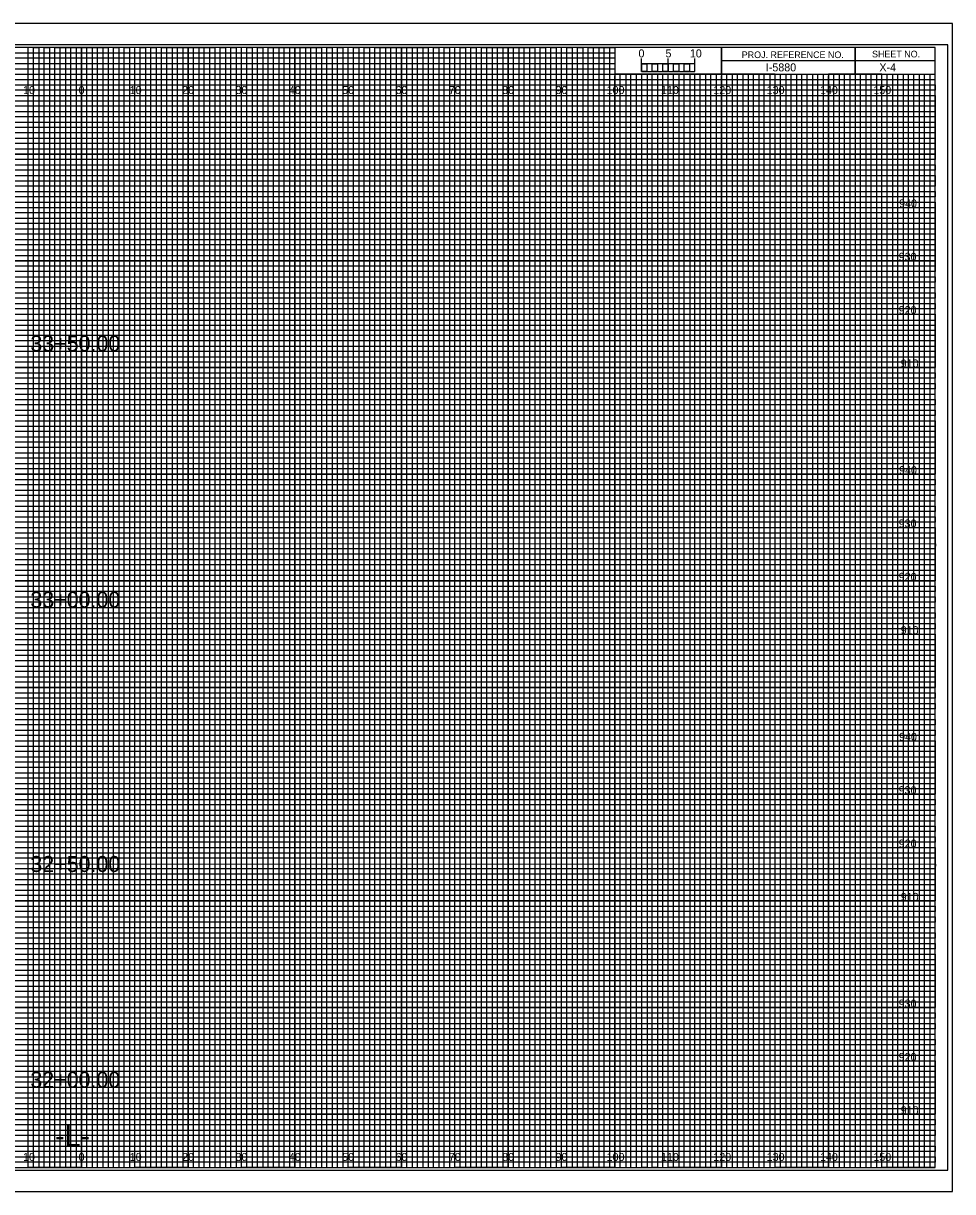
# Model space of a CAD drawing. Extents: x -13 to 323, y -4 to 3074.
# Drawn here: x 149.1 to 323.3, y 435.5 to 654.5 of the extents above; entities that cross this region are included whole.
import ezdxf

# ---------------------------------------------------------------- set-up
doc = ezdxf.new("R2010")
doc.units = 0
for name, color, linetype in [('Prop XS Alignment Label', 7, 'Continuous'), ('Prop XS Bar Scale Labels', 7, 'Continuous'), ('Prop XS Elevation Labels', 7, 'Continuous'), ('Prop XS Offset Labels', 7, 'Continuous'), ('Prop XS Project Number', 7, 'Continuous'), ('Prop XS Sheet Number', 7, 'Continuous'), ('Prop XS Station Labels', 7, 'Continuous'), ('Sheet Cross Section CELL', 7, 'Continuous'), ('Sheet Cross Section Grid Major CELL', 7, 'Continuous'), ('Sheet Cross Section Grid Middle CELL', 7, 'Continuous'), ('Sheet Cross Section Grid Minor 1 CELL', 7, 'Continuous'), ('Sheet Cross Section Grid Minor 2 CELL', 7, 'Continuous'), ('Sheet Cross Section Scale CELL', 7, 'Continuous'), ('Sheet Cutting Line CELL', 7, 'Continuous'), ('Sheet DOT Grid CELL', 7, 'Continuous'), ('Sheet Plot Border Inside CELL', 7, 'Continuous'), ('Sheet Plot Border Outside CELL', 7, 'Continuous')]:
    doc.layers.add(name, color=color, linetype=linetype)

msp = doc.modelspace()

# ---------------------------------------------------------------- linework, layer by layer
at = {"layer": 'Sheet Cross Section CELL'}
for p, q in [((305, 650), (305, 645)), ((305, 645), (305, 650)), ((280, 647.5), (280, 645)), ((320, 647.49), (280, 647.49)), ((280, 645), (320, 645))]:
    msp.add_line(p, q, dxfattribs=at)
for points in [[(320, 650), (0, 650), (0, 440), (320, 440)], [(280, 650), (260, 650), (260, 645.03), (280, 645.03)], [(320, 650), (280, 650), (280, 645), (320, 645)]]:
    msp.add_lwpolyline(points, close=True, dxfattribs=at)
at = {"layer": 'Sheet Cross Section Grid Major CELL'}
for p, q in [((150, 650), (140, 650)), ((150, 440), (150, 650)), ((170, 650), (160, 650)), ((160, 650), (160, 440)), ((170, 440), (170, 650)), ((190, 650), (180, 650)), ((180, 650), (180, 440)), ((190, 440), (190, 650)), ((210, 650), (200, 650)), ((200, 650), (200, 440)), ((210, 440), (210, 650)), ((230, 650), (220, 650)), ((220, 650), (220, 440)), ((230, 440), (230, 650)), ((250, 650), (240, 650)), ((240, 650), (240, 440)), ((250, 440), (250, 650)), ((260, 650), (260, 440)), ((270, 440), (270, 645)), ((290, 645), (280, 645)), ((280, 645), (280, 440)), ((290, 440), (290, 645)), ((310, 645), (300, 645)), ((300, 645), (300, 440)), ((310, 440), (310, 645)), ((160, 440), (150, 440)), ((180, 440), (170, 440)), ((200, 440), (190, 440)), ((220, 440), (210, 440)), ((240, 440), (230, 440)), ((260, 440), (250, 440)), ((280, 440), (270, 440)), ((300, 440), (290, 440)), ((320, 440), (310, 440)), ((320, 440), (320, 440))]:
    msp.add_line(p, q, dxfattribs=at)
for points in [[(0, 640), (320, 640), (320, 630), (0, 630)], [(0, 620), (320, 620), (320, 610), (0, 610)], [(0, 600), (320, 600), (320, 590), (0, 590)], [(0, 580), (320, 580), (320, 570), (0, 570)], [(0, 560), (320, 560), (320, 550), (0, 550)], [(0, 540), (320, 540), (320, 530), (0, 530)], [(0, 520), (320, 520), (320, 510), (0, 510)], [(0, 500), (320, 500), (320, 490), (0, 490)], [(0, 480), (320, 480), (320, 470), (0, 470)], [(0, 460), (320, 460), (320, 450), (0, 450)]]:
    msp.add_lwpolyline(points, dxfattribs=at)
at = {"layer": 'Sheet Cross Section Grid Middle CELL'}
for points in [[(145, 440), (155, 440), (155, 650), (165, 650), (165, 440), (175, 440), (175, 650), (185, 650), (185, 440), (195, 440), (195, 650), (205, 650), (205, 440), (215, 440), (215, 650), (225, 650), (225, 440), (235, 440), (235, 650), (245, 650), (245, 440), (255, 440), (255, 650), (259.93, 650), (260, 650), (260, 645), (264.99, 645), (264.99, 440), (275, 440), (275, 645), (285, 645), (285, 440), (295, 440), (295, 645), (305, 645), (305, 440), (315, 440), (315, 645)], [(0, 645), (275, 645)], [(0, 625), (320, 625), (320, 635), (0, 635)], [(0, 605), (320, 605), (320, 615), (0, 615)], [(0, 585), (320, 585), (320, 595), (0, 595)], [(0, 565), (320, 565), (320, 575), (0, 575)], [(0, 545), (320, 545), (320, 555), (0, 555)], [(0, 525), (320, 525), (320, 535), (0, 535)], [(0, 505), (320, 505), (320, 515), (0, 515)], [(0, 485), (320, 485), (320, 495), (0, 495)], [(0, 465), (320, 465), (320, 475), (0, 475)], [(0, 445), (320, 445), (320, 455), (0, 455)]]:
    msp.add_lwpolyline(points, dxfattribs=at)
at = {"layer": 'Sheet Cross Section Grid Minor 1 CELL'}
for p, q in [((0, 649), (260, 649)), ((260, 649), (260, 647.98)), ((260, 647.98), (0, 647.98)), ((0, 647), (260, 647)), ((260, 647), (260, 645.89)), ((260, 645.89), (0, 645.89)), ((0, 644), (320, 644))]:
    msp.add_line(p, q, dxfattribs=at)
for points in [[(0, 643), (270, 643), (320, 643), (320, 642), (0, 642)], [(0, 641), (320, 641), (320, 639), (0, 639)], [(0, 638), (320, 638), (320, 637), (0, 636.98)], [(0, 636), (320, 636), (320, 634), (0, 634)], [(0, 633), (320, 633), (320, 632), (0, 632)], [(0, 631), (320, 631), (320, 629), (0, 629)], [(0, 628), (320, 628), (320, 627), (0, 627)], [(0, 626), (320, 626), (320, 624), (0, 624)], [(0, 623), (320, 623), (320, 622), (0, 622)], [(0, 621), (320, 621), (320, 619), (0, 619)], [(0, 618), (320, 618), (320, 617), (0, 617)], [(0, 616), (320, 616), (320, 613.95), (320, 613), (320, 612), (0, 612)], [(0, 614), (320, 614), (320, 613), (0, 613)], [(0, 611), (320, 611), (320, 609), (0, 609.03)], [(0, 609.03), (320, 609), (320, 608), (0, 608)], [(0, 607), (320, 607), (320, 606), (0, 606)], [(0, 604), (320, 604), (320, 603), (0, 603)], [(0, 602), (320, 602), (320, 601), (0, 601)], [(-0.07, 598.89), (320, 598.89), (320, 597.88), (-0.07, 597.88)], [(0, 597), (320, 597), (320, 596), (0, 596)], [(0, 594), (320, 594), (320, 593), (0, 593)], [(0, 592), (320, 592), (320, 591), (0, 591)], [(0, 589), (320, 589), (320, 588), (0, 588)], [(0, 587), (320, 587), (320, 586), (0, 586)], [(0, 584), (320, 584), (320, 583), (0, 583)], [(0, 582), (320, 582), (320, 581), (0, 581)], [(0, 579), (320, 579), (319.99, 577.98), (0, 578)], [(0, 577), (320, 577), (320, 576), (0, 576)], [(0, 574), (320, 574), (320, 573), (0, 573)], [(0, 572), (320, 572), (320, 571), (0, 571)], [(0, 569), (320, 569), (320, 568), (0, 568)], [(0, 567), (320, 567), (320, 566), (0, 566)], [(0, 564), (320, 564), (320, 563), (0, 563)], [(0, 562), (320, 562), (320, 561), (0, 561)], [(0, 559), (320, 559), (320, 558), (0, 558)], [(0, 556.99), (320.07, 556.91), (320, 556), (0, 556)], [(0, 554), (320, 554), (320, 553), (0, 553)], [(0, 552), (320, 552), (320, 551), (0, 551)], [(0, 549), (320, 549), (320, 548), (0, 548)], [(0, 547), (320, 547), (320, 546), (0, 546)], [(0, 544), (320, 544), (320, 543), (0, 543)], [(0, 542), (320, 542), (320, 541), (0, 541)], [(0, 539), (320, 539), (320, 538), (0, 538)], [(0, 537), (320, 537), (320, 536), (0, 536)], [(0, 534), (320, 534), (320, 533), (0, 533)], [(0, 532), (320, 532), (320, 531), (0, 531)], [(0, 529), (320, 529), (320, 528), (0, 528)], [(0, 527), (320, 527), (320, 526), (0, 526)], [(0, 524), (320, 524), (320, 523), (0, 523)], [(0, 522), (320, 522), (320, 521), (0, 521)], [(0, 519), (320, 519), (319.99, 517.98), (0, 518)], [(0, 517), (320, 517), (320, 516), (0, 516)], [(0, 514), (320, 514), (320, 513), (0, 513)], [(0, 512), (320, 512), (320, 511), (0, 511)], [(0, 509), (320, 509), (320, 508), (0, 508)], [(0, 507), (320, 507), (320, 506), (0, 506)], [(0, 504), (320, 504), (320, 503), (0, 503)], [(0, 502), (320, 502), (320, 501), (0, 501)], [(0, 499), (320, 499), (320, 498), (0, 498)], [(0, 496.99), (320.07, 496.91), (320, 496), (0, 496)], [(0, 494), (320, 494), (320, 493), (0, 493)], [(0, 492), (320, 492), (320, 491), (0, 491)], [(0, 489), (320, 489), (320, 488), (0, 488)], [(0, 487), (320, 487), (320, 486), (0, 486)], [(0, 484), (320, 484), (320, 483), (0, 483)], [(0, 482), (320, 482), (320, 481), (0, 481)], [(0, 479), (320, 479), (320, 478), (0, 478)], [(0, 477), (320, 477), (320, 476), (0, 476)], [(0, 474), (320, 474), (320, 473), (0, 473)], [(0, 472), (320, 472), (320, 471), (0, 471)], [(0, 469), (320, 469), (320, 468), (0, 468)], [(0, 467), (320, 467), (320, 466), (0, 466)], [(0, 464), (320, 464), (320, 463), (0, 463)], [(0, 462), (320, 462), (320, 461), (0, 461)], [(0, 459), (320, 459), (320, 458), (0, 458)], [(0, 457), (320, 457), (320, 456), (0, 456)], [(0, 454), (320, 454), (320, 453), (0, 453)], [(0, 452), (320, 452), (320, 451), (0, 451)], [(0, 449), (320, 449), (320, 448), (0, 448)], [(0, 447), (320, 447), (320, 446), (0, 446)], [(0, 444), (320, 444), (320, 443), (0, 443)], [(0, 442), (320, 442), (320, 441), (0, 441)]]:
    msp.add_lwpolyline(points, dxfattribs=at)
at = {"layer": 'Sheet Cross Section Grid Minor 2 CELL'}
for p, q in [((267, 645), (266.01, 645)), ((266.01, 645), (266.01, 440)), ((267, 440), (267, 645)), ((269, 645), (268, 645)), ((268, 645), (268, 440)), ((269, 440), (269, 645)), ((266.01, 440), (265, 440)), ((268, 440), (267, 440))]:
    msp.add_line(p, q, dxfattribs=at)
for points in [[(150, 440), (151, 440), (151, 650), (152, 650), (152, 440)], [(152, 440), (153, 440), (153, 650), (154, 650), (154, 440)], [(155, 440), (156, 440), (156, 650), (157, 650), (157, 440)], [(157, 440), (158, 440), (158, 650), (159, 650), (159, 440)], [(160, 440), (161, 440), (161, 650), (162, 650), (162, 440)], [(162, 440), (163, 440), (163, 650), (164, 650), (164, 440)], [(165, 440), (166, 440), (166, 650), (167, 650), (167, 440)], [(167, 440), (168, 440), (168, 650), (169, 650), (169, 440)], [(170, 440), (171, 440), (171, 650), (172, 650), (172, 440)], [(172, 440), (173, 440), (173, 650), (174, 650), (174, 440)], [(175, 440), (176, 440), (176, 650), (177, 650), (177, 440)], [(177, 440), (178, 440), (178, 650), (179, 650), (179, 440)], [(180, 440), (181, 440), (181, 650), (182, 650), (182, 440)], [(182, 440), (183, 440), (183, 650), (184, 650), (184, 440)], [(185, 440), (186, 440), (186, 650), (187, 650), (187, 440)], [(187, 440), (188, 440), (188, 650), (189, 650), (189, 440)], [(190, 440), (191, 440), (191, 650), (192, 650), (192, 440)], [(192, 440), (193, 440), (193, 650), (194, 650), (194, 440)], [(195, 440), (196, 440), (196, 650), (197, 650), (197, 440)], [(197, 440), (198, 440), (198, 650), (199, 650), (199, 440)], [(200, 440), (201, 440), (201, 650), (202, 650), (202, 440)], [(202, 440), (203, 440), (203, 650), (204, 650), (204, 440)], [(205, 440), (206, 440), (206, 650), (207, 650), (207, 440)], [(207, 440), (208, 440), (208, 650), (209, 650), (209, 440)], [(210, 440), (211, 440), (211, 650), (212, 650), (212, 440)], [(212, 440), (213, 440), (213, 650), (214, 650), (214, 440)], [(215, 440), (216, 440), (216, 650), (217, 650), (217, 440)], [(217, 440), (218, 440), (218, 650), (219, 650), (219, 440)], [(220, 440), (221, 440), (221, 650), (222, 650), (222, 440)], [(222, 440), (223, 440), (223, 650), (224, 650), (224, 440)], [(225, 440), (226, 440), (226, 650), (227, 650), (227, 440)], [(227, 440), (228, 440), (228, 650), (229, 650), (229, 440)], [(230, 440), (231, 440), (231, 650), (232, 650), (232, 440)], [(232, 440), (233, 440), (233, 650), (234, 650), (234, 440)], [(235, 440), (236, 440), (236, 650), (237, 650), (237, 440)], [(237, 440), (238, 440), (238, 650), (239, 650), (239, 440)], [(240, 440), (241, 440), (241, 650), (242, 650), (242, 440)], [(242, 440), (243, 440), (243, 650), (244, 650), (244, 440)], [(245, 440), (246, 440), (246, 650), (247, 650), (247, 440)], [(247, 440), (248, 440), (248, 650), (249, 650), (249, 440)], [(250, 440), (251, 440), (251, 650), (252, 650), (252, 440)], [(252, 440), (253, 440), (253, 650), (254, 650), (254, 440)], [(255, 440), (256, 440), (256, 650), (257, 650), (257, 440)], [(257, 440), (258, 440), (258, 650), (259, 650), (259, 440)], [(260, 440), (261, 440), (261, 645), (262.02, 645), (262.02, 440)], [(262, 440), (263, 440), (263, 645), (263.99, 645), (263.99, 440)], [(270, 440), (270.98, 440), (270.98, 645), (272, 645), (272, 440)], [(272, 440), (273, 440), (273, 645), (274.05, 645), (274.05, 440)], [(275, 440), (276, 440), (276, 645), (277, 645), (277, 440)], [(277, 440), (278, 440), (278, 645), (279, 645), (279, 440)], [(280, 440), (281, 440), (281, 645), (282, 645), (282, 440)], [(282, 440), (283, 440), (283, 645), (284, 645), (284, 440)], [(285, 440), (286, 440), (286, 645), (287, 645), (287, 440)], [(287, 440), (288, 440), (288, 645), (289, 645), (289, 440)], [(290, 440), (291, 440), (291, 645), (292, 645), (292, 440)], [(292, 440), (293, 440), (293, 645), (294, 645), (294, 440)], [(295, 440), (296, 440), (296, 645), (297, 645), (297, 440)], [(297, 440), (298, 440), (298, 645), (299, 645), (299, 440)], [(300, 440), (301, 440), (301, 645), (302, 645), (302, 440)], [(302, 440), (303, 440), (303, 645), (304, 645), (304, 440)], [(305, 440), (306, 440), (306, 645), (307, 645), (307, 440)], [(307, 440), (308, 440), (308, 645), (309, 645), (309, 440)], [(310, 440), (311, 440), (311, 645), (312, 645), (312, 440)], [(312, 440), (313, 440), (313, 645), (314, 645), (314, 440)], [(315, 440), (316, 440), (316, 645), (317, 645), (317, 440)], [(317, 440), (318, 440), (318, 645), (319, 645), (319, 440)]]:
    msp.add_lwpolyline(points, dxfattribs=at)
at = {"layer": 'Sheet Cross Section Scale CELL'}
for p, q in [((265, 645.49), (265, 647.9)), ((265, 646.9), (265, 647.9)), ((270, 645.49), (270, 647.9)), ((275, 645.49), (275, 647.9)), ((275, 646.9), (275, 647.9))]:
    msp.add_line(p, q, dxfattribs=at)
for points in [[(275, 646.9), (265, 646.9), (265, 645.49), (275, 645.49)], [(265, 646.9), (266, 646.9), (266, 645.49), (265, 645.49)], [(267, 646.9), (268, 646.9), (268, 645.49), (267, 645.49)], [(269, 646.9), (270, 646.9), (270, 645.49), (269, 645.49)], [(271, 646.9), (272, 646.9), (272, 645.49), (271, 645.49)], [(273, 646.9), (274, 646.9), (274, 645.49), (273, 645.49)]]:
    msp.add_lwpolyline(points, close=True, dxfattribs=at)
at = {"layer": 'Sheet Cutting Line CELL'}
for p, q in [((323.3, 654.5), (-13.4, 654.5)), ((-13.4, 435.5), (323.3, 435.5))]:
    msp.add_line(p, q, dxfattribs=at)
at = {"layer": 'Sheet DOT Grid CELL'}
for p, q in [((150, 440), (150, 650)), ((160, 440), (160, 650)), ((170, 440), (170, 650)), ((180, 440), (180, 650)), ((190, 440), (190, 650)), ((200, 440), (200, 650)), ((210, 440), (210, 650)), ((220, 440), (220, 650)), ((230, 440), (230, 650)), ((240, 440), (240, 650)), ((250, 440), (250, 650)), ((260, 440), (260, 644.69)), ((270, 440), (270, 644.69)), ((280, 440), (280, 644.69)), ((290, 440), (290, 644.69)), ((300, 440), (300, 644.69)), ((310, 440), (310, 644.69)), ((0, 640), (320, 640)), ((0, 630), (320, 630)), ((0, 620), (320, 620)), ((0, 610), (320, 610)), ((0, 600), (320, 600)), ((0, 590), (320, 590)), ((0, 580), (320, 580)), ((0, 570), (320, 570)), ((0, 560), (320, 560)), ((0, 550), (320, 550)), ((0, 540), (320, 540)), ((0, 530), (320, 530)), ((0, 520), (320, 520)), ((0, 510), (320, 510)), ((0, 500), (320, 500)), ((0, 490), (320, 490)), ((0, 480), (320, 480)), ((0, 470), (320, 470)), ((0, 460), (320, 460)), ((0, 450), (320, 450))]:
    msp.add_line(p, q, dxfattribs=at)
at = {"layer": 'Sheet Plot Border Inside CELL'}
msp.add_lwpolyline([(-10.8, 439.5), (322.4, 439.5), (322.4, 650.5), (-10.8, 650.5)], close=True, dxfattribs=at)
at = {"layer": 'Sheet Plot Border Outside CELL'}
msp.add_lwpolyline([(-13.4, 435.5), (323.3, 435.5), (323.3, 654.5), (-13.4, 654.5)], close=True, dxfattribs=at)

# ---------------------------------------------------------------- texts
at = {"layer": 'Prop XS Alignment Label'}
msp.add_text('-L-', height=4, dxfattribs=at).set_placement((155.06, 444))
at = {"layer": 'Prop XS Bar Scale Labels'}
for s, p in [('5', (269.47, 648.12)), ('10', (274.04, 648.12))]:
    msp.add_text(s, height=1.5, dxfattribs=at).set_placement(p)
at = {"layer": 'Prop XS Elevation Labels'}
for s, p in [('940', (313.26, 620)), ('930', (313.18, 610)), ('920', (313.19, 600)), ('910', (313.57, 590)), ('940', (313.26, 570)), ('930', (313.18, 560)), ('920', (313.19, 550)), ('910', (313.57, 540)), ('940', (313.26, 520)), ('930', (313.18, 510)), ('920', (313.19, 500)), ('910', (313.57, 490)), ('930', (313.18, 470)), ('920', (313.19, 460)), ('910', (313.57, 450))]:
    msp.add_text(s, height=1.5, dxfattribs=at).set_placement(p)
at = {"layer": 'Prop XS Offset Labels'}
for s, p in [('10', (149.04, 641.25)), ('0', (159.45, 641.25)), ('0', (159.45, 641.25)), ('10', (169.04, 641.25)), ('20', (178.86, 641.25)), ('30', (188.86, 641.25)), ('40', (198.86, 641.25)), ('50', (208.86, 641.25)), ('60', (218.86, 641.25)), ('70', (228.86, 641.25)), ('80', (238.86, 641.25)), ('90', (248.86, 641.25)), ('100', (258.44, 641.25)), ('110', (268.62, 641.25)), ('120', (278.44, 641.25)), ('130', (288.44, 641.25)), ('140', (298.44, 641.25)), ('150', (308.44, 641.25)), ('10', (149.04, 441.25)), ('0', (159.45, 441.25)), ('0', (159.45, 441.25)), ('10', (169.04, 441.25)), ('20', (178.86, 441.25)), ('30', (188.86, 441.25)), ('40', (198.86, 441.25)), ('50', (208.86, 441.25)), ('60', (218.86, 441.25)), ('70', (228.86, 441.25)), ('80', (238.86, 441.25)), ('90', (248.86, 441.25)), ('100', (258.44, 441.25)), ('110', (268.62, 441.25)), ('120', (278.44, 441.25)), ('130', (288.44, 441.25)), ('140', (298.44, 441.25)), ('150', (308.44, 441.25))]:
    msp.add_text(s, height=1.5, dxfattribs=at).set_placement(p)
at = {"layer": 'Prop XS Project Number'}
msp.add_text('I-5880', height=1.5, dxfattribs=at).set_placement((288.28, 645.5))
at = {"layer": 'Prop XS Sheet Number'}
msp.add_text('X-4', height=1.5, dxfattribs=at).set_placement((309.57, 645.5))
at = {"layer": 'Prop XS Station Labels'}
for s, p in [('33+50.00', (150.41, 593)), ('33+00.00', (150.41, 544.97)), ('32+50.00', (150.41, 495.42)), ('32+00.00', (150.41, 454.98))]:
    msp.add_text(s, height=3, dxfattribs=at).set_placement(p)
at = {"layer": 'Sheet Cross Section CELL'}
for s, p in [('PROJ. REFERENCE NO.', (283.77, 647.99)), ('SHEET NO.', (308.19, 648.12))]:
    msp.add_text(s, height=1.25, dxfattribs=at).set_placement(p)
at = {"layer": 'Sheet Cross Section Scale CELL'}
msp.add_text('0', height=1.5, dxfattribs=at).set_placement((264.41, 648.12))

doc.saveas('drawing.dxf')
